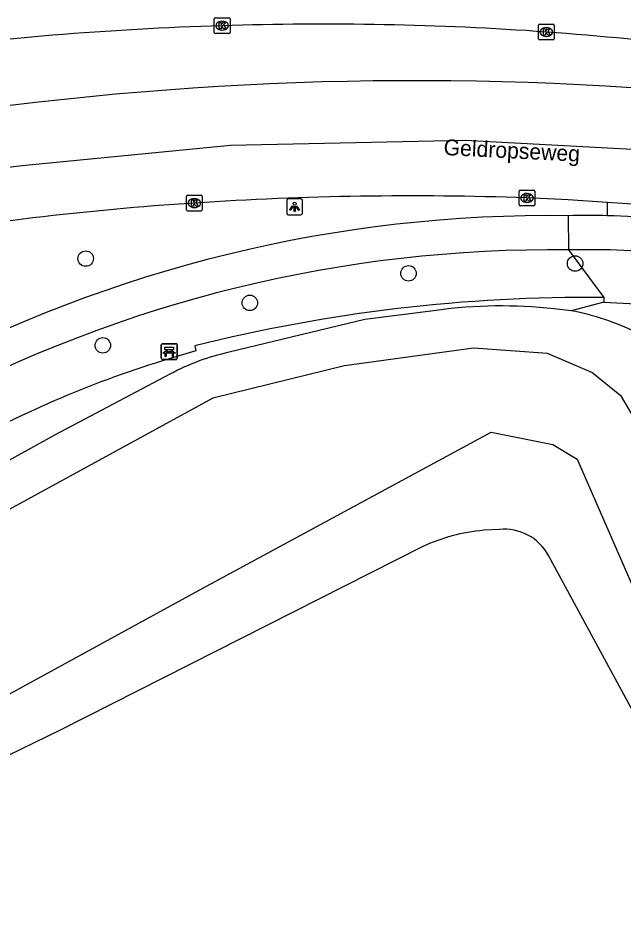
# Model space of a CAD drawing. Extents: x 162074 to 163034, y 381824 to 382557.
# Drawn here: x 162697.9 to 162736.2, y 382488.8 to 382545 of the extents above; entities that cross this region are included whole.
import ezdxf

# ---------------------------------------------------------------- set-up
doc = ezdxf.new("R2010")
doc.units = 0
for name, color, linetype in [('IMGEO_Bank', 7, 'Continuous'), ('IMGEO_Boom', 7, 'Continuous'), ('IMGEO_Erf', 7, 'Continuous'), ('IMGEO_Fietspad_gesloten', 7, 'Continuous'), ('IMGEO_Groenvoorziening', 7, 'Continuous'), ('IMGEO_Kolk', 7, 'Continuous'), ('IMGEO_Lichtpunt', 7, 'Continuous'), ('IMGEO_Meer_plas_ven_vijver', 7, 'Continuous'), ('IMGEO_Openbare_ruimte_label', 7, 'Continuous'), ('IMGEO_OVBaan_gesloten', 7, 'Continuous'), ('IMGEO_Rijbaan_lokaal_gesloten', 7, 'Continuous'), ('IMGEO_Voetpad_open', 7, 'Continuous')]:
    doc.layers.add(name, color=color, linetype=linetype)

msp = doc.modelspace()

# ---------------------------------------------------------------- linework, layer by layer
at = {"layer": 'IMGEO_Bank'}
for p, q in [((162706.999, 382523.488), (162706.999, 382524.329)), ((162706.999, 382524.329), (162706.999, 382523.488)), ((162707.074, 382524.413), (162707.915, 382524.413)), ((162707.915, 382524.413), (162707.074, 382524.413)), ((162707.999, 382524.338), (162707.999, 382523.497)), ((162707.999, 382523.497), (162707.999, 382524.338)), ((162707.696, 382523.811), (162707.303, 382523.811)), ((162707.308, 382523.919), (162707.308, 382524.025)), ((162707.352, 382524.025), (162707.352, 382523.919)), ((162707.64, 382524.031), (162707.358, 382524.031)), ((162707.358, 382523.913), (162707.64, 382523.913)), ((162707.646, 382523.919), (162707.646, 382524.025)), ((162707.69, 382524.025), (162707.69, 382523.919)), ((162707.924, 382523.413), (162707.083, 382523.413)), ((162707.083, 382523.413), (162707.924, 382523.413))]:
    msp.add_line(p, q, dxfattribs=at)
for points in [[(162707.302, 382524.031), (162707.216, 382524.031), (162707.216, 382524.192), (162707.779, 382524.192), (162707.779, 382524.031), (162707.696, 382524.031)], [(162707.246, 382523.811), (162707.104, 382523.811), (162707.216, 382523.913), (162707.302, 382523.913)], [(162707.296, 382523.804), (162707.296, 382523.597), (162707.253, 382523.597), (162707.253, 382523.804)], [(162707.696, 382523.913), (162707.779, 382523.913), (162707.891, 382523.811), (162707.752, 382523.811)], [(162707.746, 382523.804), (162707.746, 382523.597), (162707.702, 382523.597), (162707.702, 382523.804)]]:
    msp.add_lwpolyline(points, dxfattribs=at)
for centre, radius, start, end in [((162707.077, 382524.335), 0.0779, 92.4484, 184.2845), ((162707.077, 382524.335), 0.0779, 92.4484, 184.2845), ((162707.921, 382524.335), 0.0779, 2.4484, 94.2845), ((162707.921, 382524.335), 0.0779, 2.4484, 94.2845), ((162707.246, 382523.804), 0.00671, 2.8957, 87.1043), ((162707.303, 382523.804), 0.00671, 92.8957, 177.1043), ((162707.301, 382524.024), 0.00671, 2.8957, 87.1043), ((162707.301, 382523.92), 0.00671, 272.8957, 357.1043), ((162707.358, 382524.024), 0.00671, 92.8957, 177.1043), ((162707.358, 382523.92), 0.00671, 182.8957, 267.1043), ((162707.64, 382524.024), 0.00671, 2.8957, 87.1043), ((162707.64, 382523.92), 0.00671, 272.8957, 357.1043), ((162707.697, 382524.024), 0.00671, 92.8957, 177.1043), ((162707.697, 382523.92), 0.00671, 182.8957, 267.1043), ((162707.695, 382523.804), 0.00671, 2.8957, 87.1043), ((162707.752, 382523.804), 0.00671, 92.8957, 177.1043), ((162707.077, 382523.491), 0.0779, 182.4484, 274.2845), ((162707.077, 382523.491), 0.0779, 182.4484, 274.2845), ((162707.921, 382523.491), 0.0779, 272.4484, 4.2845), ((162707.921, 382523.491), 0.0779, 272.4484, 4.2845)]:
    msp.add_arc(centre, radius, start, end, dxfattribs=at)
at = {"layer": 'IMGEO_Boom'}
for centre in [(162702.22, 382529.789), (162733.149, 382529.475), (162722.62, 382528.856), (162712.595, 382526.991), (162703.305, 382524.304)]:
    msp.add_circle(centre, 0.489, dxfattribs=at)
at = {"layer": 'IMGEO_Erf'}
for points in [[(162728.37, 382512.682), (162727.372, 382512.62)], [(162723.486, 382511.574), (162700.616, 382500), (162680.832, 382490.365), (162652.758, 382475.322), (162628.647, 382462.634)], [(162760.275, 382457.733), (162760.001, 382457.819), (162754.606, 382467.605), (162747.697, 382481.037), (162737.441, 382500), (162731.475, 382511.03)]]:
    msp.add_lwpolyline(points, dxfattribs=at)
for centre, radius, start, end in [((162728.394, 382501.082), 11.583, 95.0612, 115.0694), ((162728.648, 382509.461), 3.233, 29.036, 94.9341)]:
    msp.add_arc(centre, radius, start, end, dxfattribs=at)
at = {"layer": 'IMGEO_Fietspad_gesloten'}
msp.add_lwpolyline([(162732.715, 382532.499), (162732.726, 382530.335)], dxfattribs=at)
for centre, radius, start, end in [((162731.562, 382446.737), 85.77, 89.2295, 118.22426), ((162733.924, 382476.334), 56.178, 88.7206, 91.2328), ((162733.917, 382477.155), 55.357, 85.0874, 88.6952), ((162731.674, 382446.63), 83.712, 89.27985, 118.24096), ((162734.043, 382479.478), 50.874, 75.6965, 91.4836)]:
    msp.add_arc(centre, radius, start, end, dxfattribs=at)
at = {"layer": 'IMGEO_Groenvoorziening'}
for points in [[(162734.968, 382527.031), (162732.911, 382526.489)], [(162724.376, 382526.516), (162719.87, 382525.936), (162711.28, 382523.868)], [(162732.911, 382526.489), (162731.818, 382526.611)], [(162707.587, 382522.5), (162700.301, 382518.645), (162688.744, 382512.261), (162667.531, 382500), (162647.923, 382488.667), (162632.054, 382479.755)]]:
    msp.add_lwpolyline(points, dxfattribs=at)
for centre, radius, start, end in [((162728.479, 382496.644), 30.152, 83.6419, 97.8208), ((162729.818, 382510.319), 16.463, 63.9762, 79.1706), ((162714.081, 382510.639), 13.523, 101.9532, 118.6991)]:
    msp.add_arc(centre, radius, start, end, dxfattribs=at)
at = {"layer": 'IMGEO_Kolk'}
for p, q in [((162710.343, 382544.077), (162710.343, 382544.929)), ((162710.418, 382545.003), (162711.27, 382545.003)), ((162711.344, 382544.929), (162711.344, 382544.077)), ((162710.831, 382544.783), (162710.856, 382544.783)), ((162730.829, 382543.677), (162730.829, 382544.529)), ((162730.904, 382544.603), (162731.756, 382544.603)), ((162731.317, 382544.383), (162731.342, 382544.383)), ((162731.83, 382544.529), (162731.83, 382543.677)), ((162711.27, 382544.003), (162710.418, 382544.003)), ((162710.854, 382544.223), (162710.829, 382544.223)), ((162731.34, 382543.823), (162731.315, 382543.823)), ((162731.756, 382543.603), (162730.904, 382543.603)), ((162708.584, 382532.869), (162708.584, 382533.721)), ((162708.659, 382533.795), (162709.511, 382533.795)), ((162709.585, 382533.721), (162709.585, 382532.869)), ((162729.61, 382533.195), (162729.61, 382534.047)), ((162729.685, 382534.121), (162730.537, 382534.121)), ((162730.098, 382533.901), (162730.123, 382533.901)), ((162730.611, 382534.047), (162730.611, 382533.195)), ((162709.072, 382533.575), (162709.097, 382533.575)), ((162730.537, 382533.121), (162729.685, 382533.121)), ((162730.121, 382533.341), (162730.096, 382533.341)), ((162709.511, 382532.795), (162708.659, 382532.795)), ((162709.095, 382533.015), (162709.07, 382533.015))]:
    msp.add_line(p, q, dxfattribs=at)
for points in [[(162710.343, 382544.077), (162710.343, 382544.929)], [(162710.418, 382545.003), (162711.27, 382545.003)], [(162711.344, 382544.929), (162711.344, 382544.077)], [(162710.664, 382544.703), (162710.787, 382544.703), (162710.787, 382544.552), (162710.917, 382544.703), (162711.081, 382544.703), (162710.935, 382544.552), (162711.088, 382544.303), (162710.936, 382544.303), (162710.851, 382544.467), (162710.787, 382544.4), (162710.787, 382544.303), (162710.664, 382544.303), (162710.664, 382544.703)], [(162730.829, 382543.677), (162730.829, 382544.529)], [(162730.904, 382544.603), (162731.756, 382544.603)], [(162731.83, 382544.529), (162731.83, 382543.677)], [(162711.27, 382544.003), (162710.418, 382544.003)], [(162731.15, 382544.303), (162731.273, 382544.303), (162731.273, 382544.152), (162731.403, 382544.303), (162731.567, 382544.303), (162731.421, 382544.152), (162731.574, 382543.903), (162731.422, 382543.903), (162731.337, 382544.067), (162731.273, 382544), (162731.273, 382543.903), (162731.15, 382543.903), (162731.15, 382544.303)], [(162731.756, 382543.603), (162730.904, 382543.603)], [(162708.584, 382532.869), (162708.584, 382533.721)], [(162708.659, 382533.795), (162709.511, 382533.795)], [(162709.585, 382533.721), (162709.585, 382532.869)], [(162729.61, 382533.195), (162729.61, 382534.047)], [(162729.685, 382534.121), (162730.537, 382534.121)], [(162729.931, 382533.821), (162730.054, 382533.821), (162730.054, 382533.67), (162730.184, 382533.821), (162730.348, 382533.821), (162730.202, 382533.67), (162730.355, 382533.421), (162730.203, 382533.421), (162730.118, 382533.585), (162730.054, 382533.518), (162730.054, 382533.421), (162729.931, 382533.421), (162729.931, 382533.821)], [(162730.611, 382534.047), (162730.611, 382533.195)], [(162708.905, 382533.495), (162709.028, 382533.495), (162709.028, 382533.344), (162709.158, 382533.495), (162709.322, 382533.495), (162709.176, 382533.344), (162709.329, 382533.095), (162709.177, 382533.095), (162709.092, 382533.259), (162709.028, 382533.192), (162709.028, 382533.095), (162708.905, 382533.095), (162708.905, 382533.495)], [(162730.537, 382533.121), (162729.685, 382533.121)], [(162709.511, 382532.795), (162708.659, 382532.795)]]:
    msp.add_lwpolyline(points, dxfattribs=at)
for centre, start, end in [((162710.42, 382544.927), 91.552, 178.448), ((162710.42, 382544.927), 91.552, 178.448), ((162711.268, 382544.927), 1.552, 88.448), ((162711.268, 382544.927), 1.552, 88.448), ((162730.906, 382544.527), 91.552, 178.448), ((162730.906, 382544.527), 91.552, 178.448), ((162731.754, 382544.527), 1.552, 88.448), ((162731.754, 382544.527), 1.552, 88.448), ((162710.42, 382544.079), 181.552, 268.448), ((162710.42, 382544.079), 181.552, 268.448), ((162711.268, 382544.079), 271.552, 358.448), ((162711.268, 382544.079), 271.552, 358.448), ((162730.906, 382543.679), 181.552, 268.448), ((162730.906, 382543.679), 181.552, 268.448), ((162731.754, 382543.679), 271.552, 358.448), ((162731.754, 382543.679), 271.552, 358.448), ((162708.661, 382533.719), 91.552, 178.448), ((162708.661, 382533.719), 91.552, 178.448), ((162709.509, 382533.719), 1.552, 88.448), ((162709.509, 382533.719), 1.552, 88.448), ((162729.687, 382534.045), 91.552, 178.448), ((162729.687, 382534.045), 91.552, 178.448), ((162730.535, 382534.045), 1.552, 88.448), ((162730.535, 382534.045), 1.552, 88.448), ((162729.687, 382533.197), 181.552, 268.448), ((162729.687, 382533.197), 181.552, 268.448), ((162730.535, 382533.197), 271.552, 358.448), ((162730.535, 382533.197), 271.552, 358.448), ((162708.661, 382532.871), 181.552, 268.448), ((162708.661, 382532.871), 181.552, 268.448), ((162709.509, 382532.871), 271.552, 358.448), ((162709.509, 382532.871), 271.552, 358.448)]:
    msp.add_arc(centre, 0.0765, start, end, dxfattribs=at)
for centre, major_axis, ratio, start_param, end_param in [((162710.83, 382544.503), (-0.387, 0.002), 0.722429, 4.712389, 7.853982), ((162710.855, 382544.503), (-0.39, 0.002), 0.717154, 1.570796, 4.712389), ((162731.316, 382544.103), (-0.387, 0.002), 0.722429, 4.712389, 7.853982), ((162731.341, 382544.103), (-0.39, 0.002), 0.717154, 1.570796, 4.712389), ((162730.097, 382533.621), (-0.387, 0.002), 0.722429, 4.712389, 7.853982), ((162730.122, 382533.621), (-0.39, 0.002), 0.717154, 1.570796, 4.712389), ((162709.071, 382533.295), (-0.387, 0.002), 0.722429, 4.712389, 7.853982), ((162709.096, 382533.295), (-0.39, 0.002), 0.717154, 1.570796, 4.712389)]:
    msp.add_ellipse(centre, major_axis=major_axis, ratio=ratio, start_param=start_param, end_param=end_param, dxfattribs=at)
at = {"layer": 'IMGEO_Lichtpunt'}
for p, q in [((162714.925, 382533.463), (162714.925, 382532.656)), ((162714.925, 382533.463), (162714.925, 382532.656)), ((162715.827, 382533.558), (162715.019, 382533.558)), ((162715.827, 382533.558), (162715.019, 382533.558)), ((162715.921, 382532.656), (162715.921, 382533.463)), ((162715.921, 382532.656), (162715.921, 382533.463)), ((162715.019, 382532.562), (162715.827, 382532.562)), ((162715.019, 382532.562), (162715.827, 382532.562))]:
    msp.add_line(p, q, dxfattribs=at)
for points in [[(162715.299, 382533.127), (162715.338, 382533.099), (162715.15, 382532.837), (162715.112, 382532.864), (162715.299, 382533.127)], [(162715.401, 382533.079), (162715.448, 382533.079), (162715.448, 382532.757), (162715.401, 382532.757), (162715.401, 382533.079)], [(162715.511, 382533.099), (162715.549, 382533.126), (162715.736, 382532.864), (162715.697, 382532.836), (162715.511, 382533.099)]]:
    msp.add_lwpolyline(points, dxfattribs=at)
msp.add_circle((162715.424, 382533.261), 0.0994, dxfattribs=at)
for centre, start, end in [((162715.019, 382533.463), 90, 180), ((162715.019, 382533.463), 90, 180), ((162715.827, 382533.463), 0, 90), ((162715.827, 382533.463), 0, 90), ((162715.019, 382532.656), 180, 270), ((162715.019, 382532.656), 180, 270), ((162715.827, 382532.656), 270, 0), ((162715.827, 382532.656), 270, 360)]:
    msp.add_arc(centre, 0.0946, start, end, dxfattribs=at)
at = {"layer": 'IMGEO_Meer_plas_ven_vijver'}
for points in [[(162755.094, 382483.224), (162748.731, 382498.475), (162742.234, 382510.619), (162736.077, 382521.065), (162734.208, 382522.594), (162731.406, 382523.783), (162726.735, 382524.122), (162718.582, 382523.018), (162710.259, 382520.98), (162692.849, 382511.469)], [(162630.047, 382465.439), (162709.622, 382508.963), (162727.839, 382518.815), (162731.745, 382518.05), (162733.274, 382517.116), (162737.775, 382506.84), (162760.833, 382461.193), (162763.72, 382462.551), (162755.094, 382483.224)]]:
    msp.add_lwpolyline(points, dxfattribs=at)
at = {"layer": 'IMGEO_OVBaan_gesloten'}
for points in [[(162568.138, 382498.576), (162601.758, 382507.473), (162623.526, 382515.096), (162638.589, 382520.515), (162652.734, 382524.924), (162671.93, 382530.986), (162686.717, 382534.292), (162698.199, 382535.67), (162711.379, 382536.956), (162726.212, 382537.278), (162742.24, 382536.416), (162755.489, 382534.694), (162767.039, 382532.455), (162790.552, 382526.577), (162850.851, 382511.79), (162870.874, 382506.646), (162879.507, 382503.523), (162894.571, 382498.563), (162901.643, 382496.451), (162915.42, 382492.961), (163006.626, 382470.32), (163005.936, 382467.312)], [(162735.178, 382533.342), (162732.702, 382533.505), (162730.107, 382533.622)], [(162740.553, 382532.955), (162739.644, 382533.034), (162738.734, 382533.109), (162735.178, 382533.342)]]:
    msp.add_lwpolyline(points, dxfattribs=at)
for centre, radius, start, end in [((162722.801, 382326.619), 207.132, 87.97863, 93.79793), ((162721.538, 382342.527), 191.175, 93.73615, 99.87133)]:
    msp.add_arc(centre, radius, start, end, dxfattribs=at)
at = {"layer": 'IMGEO_Rijbaan_lokaal_gesloten'}
for centre, radius, start, end in [((162717.412, 382333.644), 210.962, 91.7852, 97.61478), ((162717.206, 382345.723), 198.882, 85.92865, 91.83417), ((162718.686, 382367.939), 176.618, 79.24944, 85.89595), ((162723.049, 382332.728), 208.303, 79.9282, 108.71355)]:
    msp.add_arc(centre, radius, start, end, dxfattribs=at)
at = {"layer": 'IMGEO_Voetpad_open'}
for points in [[(162735.178, 382533.342), (162735.178, 382532.498)], [(162732.726, 382530.335), (162734.956, 382527.332)], [(162734.956, 382527.332), (162734.968, 382527.031)], [(162734.968, 382527.031), (162736.978, 382526.932)], [(162709.111, 382524.272), (162709.185, 382523.967), (162707.067, 382523.321)]]:
    msp.add_lwpolyline(points, dxfattribs=at)
for centre, radius, start, end in [((162733.968, 382425.005), 102.332, 89.44661, 104.05795), ((162726.397, 382460.353), 65.868, 107.06514, 119.75975)]:
    msp.add_arc(centre, radius, start, end, dxfattribs=at)

# ---------------------------------------------------------------- texts
at = {"layer": 'IMGEO_Openbare_ruimte_label'}
msp.add_text('Geldropseweg', height=1, rotation=357.1919, dxfattribs=at).set_placement((162724.822, 382536.334))

doc.saveas('drawing.dxf')
